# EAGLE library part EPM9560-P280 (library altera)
EPM9560 MAX 9000 family
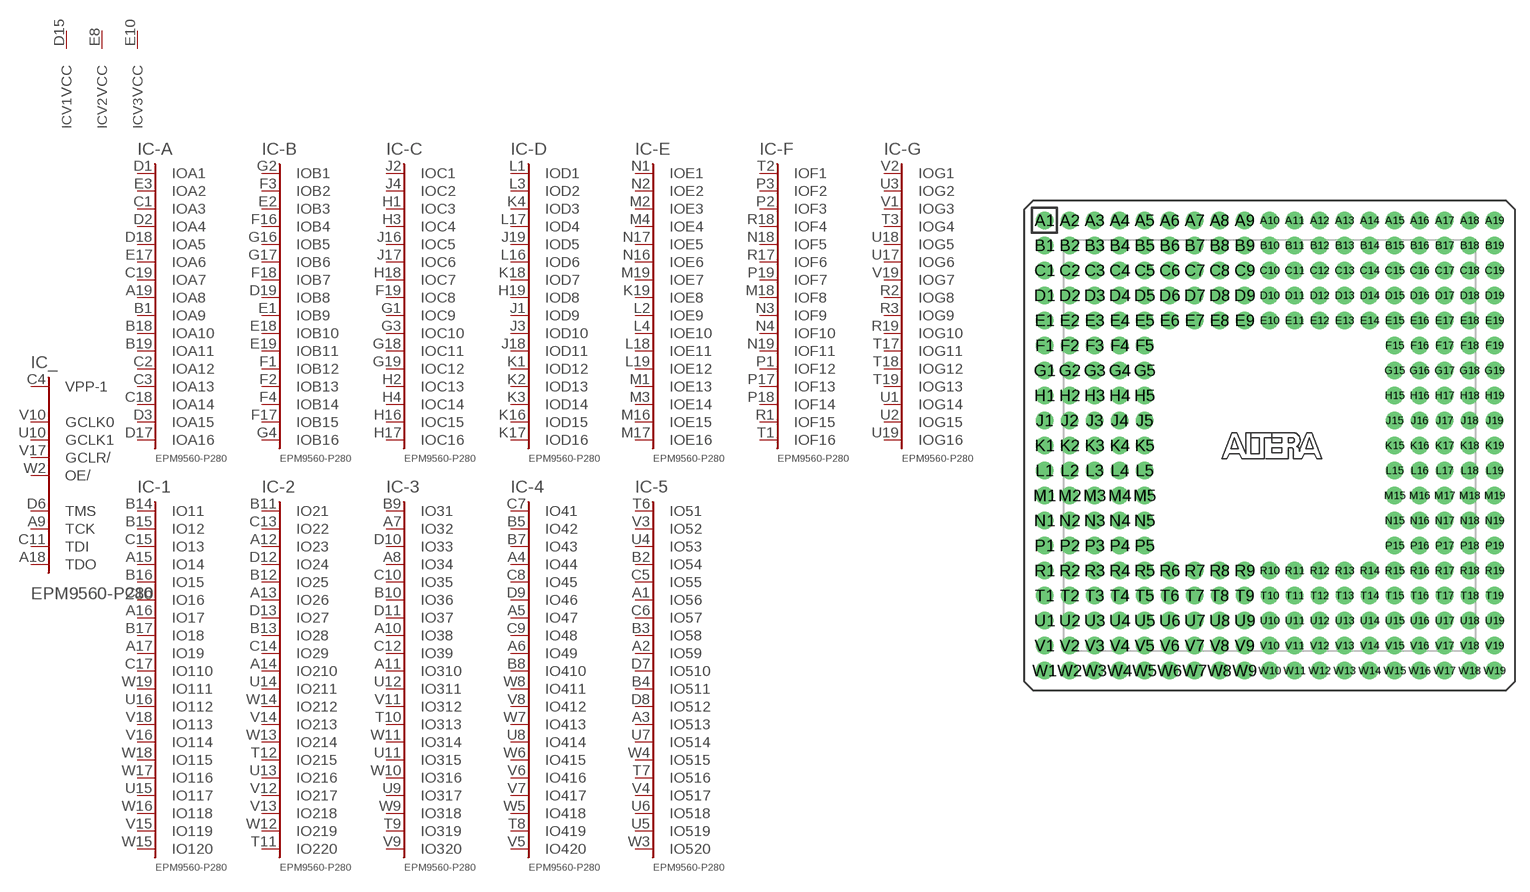
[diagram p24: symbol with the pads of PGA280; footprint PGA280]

Designator prefix IC; gates _=9560C356 -A=A16-0 -B=B16-0 -C=C16-0 -D=D16-0 -E=E16-0 -F=F16-0 -G=G16-0 -1=IO120 -2=IO220 -3=IO320 -4=IO420 -5=IO520 V1=VCCINT V2=VCCINT V3=VCCINT V4=VCCINT V5=VCCINT V6=VCCINT V7=VCCINT V8=VCCINT V9=VCCINT V10=VCCINT V11=VCCINT VO1=VCCIO VO2=VCCIO VO3=VCCIO VO4=VCCIO VO5=VCCIO VO6=VCCIO VO7=VCCIO VO8=VCCIO VO9=VCCIO VO10=VCCIO VO11=VCCIO G1=GND G2=GND G3=GND G4=GND G5=GND G6=GND G7=GND G8=GND G9=GND G10=GND G11=GND G12=GND G13=GND G14=GND G15=GND G16=GND G17=GND G18=GND G19=GND G20=GND G21=GND G22=GND G23=GND G24=GND G25=GND G26=GND G27=GND G28=GND G29=GND G30=GND G31=GND G32=GND G33=GND G34=GND G35=GND NC1=NC NC2=NC

## EPM9560-P280 (OC_FARNELL: unknown; OC_NEWARK: unknown)  [PGA280]
A1  -5:IO56
A2  -5:IO59
A3  -5:IO513
A4  -4:IO44
A5  -4:IO47
A6  -4:IO49
A7  -3:IO32
A8  -3:IO34
A9  _:TCK
A10  -3:IO38
A11  -3:IO310
A12  -2:IO23
A13  -2:IO26
A14  -2:IO210
A15  -1:IO14
A16  -1:IO17
A17  -1:IO19
A18  _:TDO
A19  -A:IOA8
B1  -A:IOA9
B2  -5:IO54
B3  -5:IO58
B4  -5:IO511
B5  -4:IO42
B6  NC1:NC  nc
B7  -4:IO43
B8  -4:IO410
B9  -3:IO31
B10  -3:IO36
B11  -2:IO21
B12  -2:IO25
B13  -2:IO28
B14  -1:IO11
B15  -1:IO12
B16  -1:IO15
B17  -1:IO18
B18  -A:IOA10
B19  -A:IOA11
C1  -A:IOA3
C2  -A:IOA12
C3  -A:IOA13
C4  _:VPP-1  in
C5  -5:IO55
C6  -5:IO57
C7  -4:IO41
C8  -4:IO45
C9  -4:IO48
C10  -3:IO35
C11  _:TDI
C12  -3:IO39
C13  -2:IO22
C14  -2:IO29
C15  -1:IO13
C16  -1:IO16
C17  -1:IO110
C18  -A:IOA14
C19  -A:IOA7
D1  -A:IOA1
D2  -A:IOA4
D3  -A:IOA15
D4  G1:GND  pwr
D5  G2:GND  pwr
D6  _:TMS
D7  -5:IO510
D8  -5:IO512
D9  -4:IO46
D10  -3:IO33
D11  -3:IO37
D12  -2:IO24
D13  -2:IO27
D14  VO1:VCCIO  pwr
D15  V1:VCC  pwr
D16  G3:GND  pwr
D17  -A:IOA16
D18  -A:IOA5
D19  -B:IOB8
E1  -B:IOB9
E2  -B:IOB3
E3  -A:IOA2
E4  G4:GND  pwr
E5  G5:GND  pwr
E6  G6:GND  pwr
E7  VO2:VCCIO  pwr
E8  V2:VCC  pwr
E9  VO3:VCCIO  pwr
E10  V3:VCC  pwr
E11  VO4:VCCIO  pwr
E12  V4:VCC  pwr
E13  VO5:VCCIO  pwr
E14  V5:VCC  pwr
E15  G7:GND  pwr
E16  G8:GND  pwr
E17  -A:IOA6
E18  -B:IOB10
E19  -B:IOB11
F1  -B:IOB12
F2  -B:IOB13
F3  -B:IOB2
F4  -B:IOB14
F5  G9:GND  pwr
F15  G10:GND  pwr
F16  -B:IOB4
F17  -B:IOB15
F18  -B:IOB7
F19  -C:IOC8
G1  -C:IOC9
G2  -B:IOB1
G3  -C:IOC10
G4  -B:IOB16
G5  G11:GND  pwr
G15  G12:GND  pwr
G16  -B:IOB5
G17  -B:IOB6
G18  -C:IOC11
G19  -C:IOC12
H1  -C:IOC3
H2  -C:IOC13
H3  -C:IOC4
H4  -C:IOC14
H5  G13:GND  pwr
H15  G14:GND  pwr
H16  -C:IOC15
H17  -C:IOC16
H18  -C:IOC7
H19  -D:IOD8
J1  -D:IOD9
J2  -C:IOC1
J3  -D:IOD10
J4  -C:IOC2
J5  G15:GND  pwr
J15  G16:GND  pwr
J16  -C:IOC5
J17  -C:IOC6
J18  -D:IOD11
J19  -D:IOD5
K1  -D:IOD12
K2  -D:IOD13
K3  -D:IOD14
K4  -D:IOD3
K5  G17:GND  pwr
K15  G18:GND  pwr
K16  -D:IOD15
K17  -D:IOD16
K18  -D:IOD7
K19  -E:IOE8
L1  -D:IOD1
L2  -E:IOE9
L3  -D:IOD2
L4  -E:IOE10
L5  G19:GND  pwr
L15  G20:GND  pwr
L16  -D:IOD6
L17  -D:IOD4
L18  -E:IOE11
L19  -E:IOE12
M1  -E:IOE13
M2  -E:IOE3
M3  -E:IOE14
M4  -E:IOE4
M5  G21:GND  pwr
M15  G22:GND  pwr
M16  -E:IOE15
M17  -E:IOE16
M18  -F:IOF8
M19  -E:IOE7
N1  -E:IOE1
N2  -E:IOE2
N3  -F:IOF9
N4  -F:IOF10
N5  G23:GND  pwr
N15  G24:GND  pwr
N16  -E:IOE6
N17  -E:IOE5
N18  -F:IOF5
N19  -F:IOF11
P1  -F:IOF12
P2  -F:IOF3
P3  -F:IOF2
P4  G25:GND  pwr
P5  G26:GND  pwr
P15  G27:GND  pwr
P16  G28:GND  pwr
P17  -F:IOF13
P18  -F:IOF14
P19  -F:IOF7
R1  -F:IOF15
R2  -G:IOG8
R3  -G:IOG9
R4  G29:GND  pwr
R5  G30:GND  pwr
R6  VO6:VCCIO  pwr
R7  V6:VCC  pwr
R8  VO7:VCCIO  pwr
R9  V7:VCC  pwr
R10  VO8:VCCIO  pwr
R11  V8:VCC  pwr
R12  VO9:VCCIO  pwr
R13  V9:VCC  pwr
R14  V10:VCC  pwr
R15  G31:GND  pwr
R16  G32:GND  pwr
R17  -F:IOF6
R18  -F:IOF4
R19  -G:IOG10
T1  -F:IOF16
T2  -F:IOF1
T3  -G:IOG4
T4  G33:GND  pwr
T5  G34:GND  pwr
T6  -5:IO51
T7  -5:IO516
T8  -4:IO419
T9  -3:IO319
T10  -3:IO313
T11  -2:IO220
T12  -2:IO215
T13  VO10:VCCIO  pwr
T14  V11:VCC  pwr
T15  VO11:VCCIO  pwr
T16  G35:GND  pwr
T17  -G:IOG11
T18  -G:IOG12
T19  -G:IOG13
U1  -G:IOG14
U2  -G:IOG15
U3  -G:IOG2
U4  -5:IO53
U5  -5:IO519
U6  -5:IO518
U7  -5:IO514
U8  -4:IO414
U9  -3:IO317
U10  _:GCLK1  in
U11  -3:IO315
U12  -3:IO311
U13  -2:IO216
U14  -2:IO211
U15  -1:IO117
U16  -1:IO112
U17  -G:IOG6
U18  -G:IOG5
U19  -G:IOG16
V1  -G:IOG3
V2  -G:IOG1
V3  -5:IO52
V4  -5:IO517
V5  -4:IO420
V6  -4:IO416
V7  -4:IO417
V8  -4:IO412
V9  -3:IO320
V10  _:GCLK0  in
V11  -3:IO312
V12  -2:IO217
V13  -2:IO218
V14  -2:IO213
V15  -1:IO119
V16  -1:IO114
V17  _:GCLR/  in
V18  -1:IO113
V19  -G:IOG7
W1  NC2:NC  nc
W2  _:OE/  in
W3  -5:IO520
W4  -5:IO515
W5  -4:IO418
W6  -4:IO415
W7  -4:IO413
W8  -4:IO411
W9  -3:IO318
W10  -3:IO316
W11  -3:IO314
W12  -2:IO219
W13  -2:IO214
W14  -2:IO212
W15  -1:IO120
W16  -1:IO118
W17  -1:IO116
W18  -1:IO115
W19  -1:IO111

## Footprint PGA280 (pad centres in mm)
Pin Grid Array
drill 0.813 pad 1.778 round: A1 -22.86,22.86; A2 -20.32,22.86; A3 -17.78,22.86; A4 -15.24,22.86; A5 -12.7,22.86; A6 -10.16,22.86; A7 -7.62,22.86; A8 -5.08,22.86; A9 -2.54,22.86; A10 0,22.86; A11 2.54,22.86; A12 5.08,22.86; A13 7.62,22.86; A14 10.16,22.86; A15 12.7,22.86; A16 15.24,22.86; A17 17.78,22.86; A18 20.32,22.86; A19 22.86,22.86; B1 -22.86,20.32; B2 -20.32,20.32; B3 -17.78,20.32; B4 -15.24,20.32; B5 -12.7,20.32; B6 -10.16,20.32; B7 -7.62,20.32; B8 -5.08,20.32; B9 -2.54,20.32; B10 0,20.32; B11 2.54,20.32; B12 5.08,20.32; B13 7.62,20.32; B14 10.16,20.32; B15 12.7,20.32; B16 15.24,20.32; B17 17.78,20.32; B18 20.32,20.32; B19 22.86,20.32; C1 -22.86,17.78; C2 -20.32,17.78; C3 -17.78,17.78; C4 -15.24,17.78; C5 -12.7,17.78; C6 -10.16,17.78; C7 -7.62,17.78; C8 -5.08,17.78; C9 -2.54,17.78; C10 0,17.78; C11 2.54,17.78; C12 5.08,17.78; C13 7.62,17.78; C14 10.16,17.78; C15 12.7,17.78; C16 15.24,17.78; C17 17.78,17.78; C18 20.32,17.78; C19 22.86,17.78; D1 -22.86,15.24; D2 -20.32,15.24; D3 -17.78,15.24; D4 -15.24,15.24; D5 -12.7,15.24; D6 -10.16,15.24; D7 -7.62,15.24; D8 -5.08,15.24; D9 -2.54,15.24; D10 0,15.24; D11 2.54,15.24; D12 5.08,15.24; D13 7.62,15.24; D14 10.16,15.24; D15 12.7,15.24; D16 15.24,15.24; D17 17.78,15.24; D18 20.32,15.24; D19 22.86,15.24; E1 -22.86,12.7; E2 -20.32,12.7; E3 -17.78,12.7; E4 -15.24,12.7; E5 -12.7,12.7; E6 -10.16,12.7; E7 -7.62,12.7; E8 -5.08,12.7; E9 -2.54,12.7; E10 0,12.7; E11 2.54,12.7; E12 5.08,12.7; E13 7.62,12.7; E14 10.16,12.7; E15 12.7,12.7; E16 15.24,12.7; E17 17.78,12.7; E18 20.32,12.7; E19 22.86,12.7; F1 -22.86,10.16; F2 -20.32,10.16; F3 -17.78,10.16; F4 -15.24,10.16; F5 -12.7,10.16; F15 12.7,10.16; F16 15.24,10.16; F17 17.78,10.16; F18 20.32,10.16; F19 22.86,10.16; G1 -22.86,7.62; G2 -20.32,7.62; G3 -17.78,7.62; G4 -15.24,7.62; G5 -12.7,7.62; G15 12.7,7.62; G16 15.24,7.62; G17 17.78,7.62; G18 20.32,7.62; G19 22.86,7.62; H1 -22.86,5.08; H2 -20.32,5.08; H3 -17.78,5.08; H4 -15.24,5.08; H5 -12.7,5.08; H15 12.7,5.08; H16 15.24,5.08; H17 17.78,5.08; H18 20.32,5.08; H19 22.86,5.08; J1 -22.86,2.54; J2 -20.32,2.54; J3 -17.78,2.54; J4 -15.24,2.54; J5 -12.7,2.54; J15 12.7,2.54; J16 15.24,2.54; J17 17.78,2.54; J18 20.32,2.54; J19 22.86,2.54; K1 -22.86,0; K2 -20.32,0; K3 -17.78,0; K4 -15.24,0; K5 -12.7,0; K15 12.7,0; K16 15.24,0; K17 17.78,0; K18 20.32,0; K19 22.86,0; L1 -22.86,-2.54; L2 -20.32,-2.54; L3 -17.78,-2.54; L4 -15.24,-2.54; L5 -12.7,-2.54; L15 12.7,-2.54; L16 15.24,-2.54; L17 17.78,-2.54; L18 20.32,-2.54; L19 22.86,-2.54; M1 -22.86,-5.08; M2 -20.32,-5.08; M3 -17.78,-5.08; M4 -15.24,-5.08; M5 -12.7,-5.08; M15 12.7,-5.08; M16 15.24,-5.08; M17 17.78,-5.08; M18 20.32,-5.08; M19 22.86,-5.08; N1 -22.86,-7.62; N2 -20.32,-7.62; N3 -17.78,-7.62; N4 -15.24,-7.62; N5 -12.7,-7.62; N15 12.7,-7.62; N16 15.24,-7.62; N17 17.78,-7.62; N18 20.32,-7.62; N19 22.86,-7.62; P1 -22.86,-10.16; P2 -20.32,-10.16; P3 -17.78,-10.16; P4 -15.24,-10.16; P5 -12.7,-10.16; P15 12.7,-10.16; P16 15.24,-10.16; P17 17.78,-10.16; P18 20.32,-10.16; P19 22.86,-10.16; R1 -22.86,-12.7; R2 -20.32,-12.7; R3 -17.78,-12.7; R4 -15.24,-12.7; R5 -12.7,-12.7; R6 -10.16,-12.7; R7 -7.62,-12.7; R8 -5.08,-12.7; R9 -2.54,-12.7; R10 0,-12.7; R11 2.54,-12.7; R12 5.08,-12.7; R13 7.62,-12.7; R14 10.16,-12.7; R15 12.7,-12.7; R16 15.24,-12.7; R17 17.78,-12.7; R18 20.32,-12.7; R19 22.86,-12.7; T1 -22.86,-15.24; T2 -20.32,-15.24; T3 -17.78,-15.24; T4 -15.24,-15.24; T5 -12.7,-15.24; T6 -10.16,-15.24; T7 -7.62,-15.24; T8 -5.08,-15.24; T9 -2.54,-15.24; T10 0,-15.24; T11 2.54,-15.24; T12 5.08,-15.24; T13 7.62,-15.24; T14 10.16,-15.24; T15 12.7,-15.24; T16 15.24,-15.24; T17 17.78,-15.24; T18 20.32,-15.24; T19 22.86,-15.24; U1 -22.86,-17.78; U2 -20.32,-17.78; U3 -17.78,-17.78; U4 -15.24,-17.78; U5 -12.7,-17.78; U6 -10.16,-17.78; U7 -7.62,-17.78; U8 -5.08,-17.78; U9 -2.54,-17.78; U10 0,-17.78; U11 2.54,-17.78; U12 5.08,-17.78; U13 7.62,-17.78; U14 10.16,-17.78; U15 12.7,-17.78; U16 15.24,-17.78; U17 17.78,-17.78; U18 20.32,-17.78; U19 22.86,-17.78; V1 -22.86,-20.32; V2 -20.32,-20.32; V3 -17.78,-20.32; V4 -15.24,-20.32; V5 -12.7,-20.32; V6 -10.16,-20.32; V7 -7.62,-20.32; V8 -5.08,-20.32; V9 -2.54,-20.32; V10 0,-20.32; V11 2.54,-20.32; V12 5.08,-20.32; V13 7.62,-20.32; V14 10.16,-20.32; V15 12.7,-20.32; V16 15.24,-20.32; V17 17.78,-20.32; V18 20.32,-20.32; V19 22.86,-20.32; W1 -22.86,-22.86; W2 -20.32,-22.86; W3 -17.78,-22.86; W4 -15.24,-22.86; W5 -12.7,-22.86; W6 -10.16,-22.86; W7 -7.62,-22.86; W8 -5.08,-22.86; W9 -2.54,-22.86; W10 0,-22.86; W11 2.54,-22.86; W12 5.08,-22.86; W13 7.62,-22.86; W14 10.16,-22.86; W15 12.7,-22.86; W16 15.24,-22.86; W17 17.78,-22.86; W18 20.32,-22.86; W19 22.86,-22.86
